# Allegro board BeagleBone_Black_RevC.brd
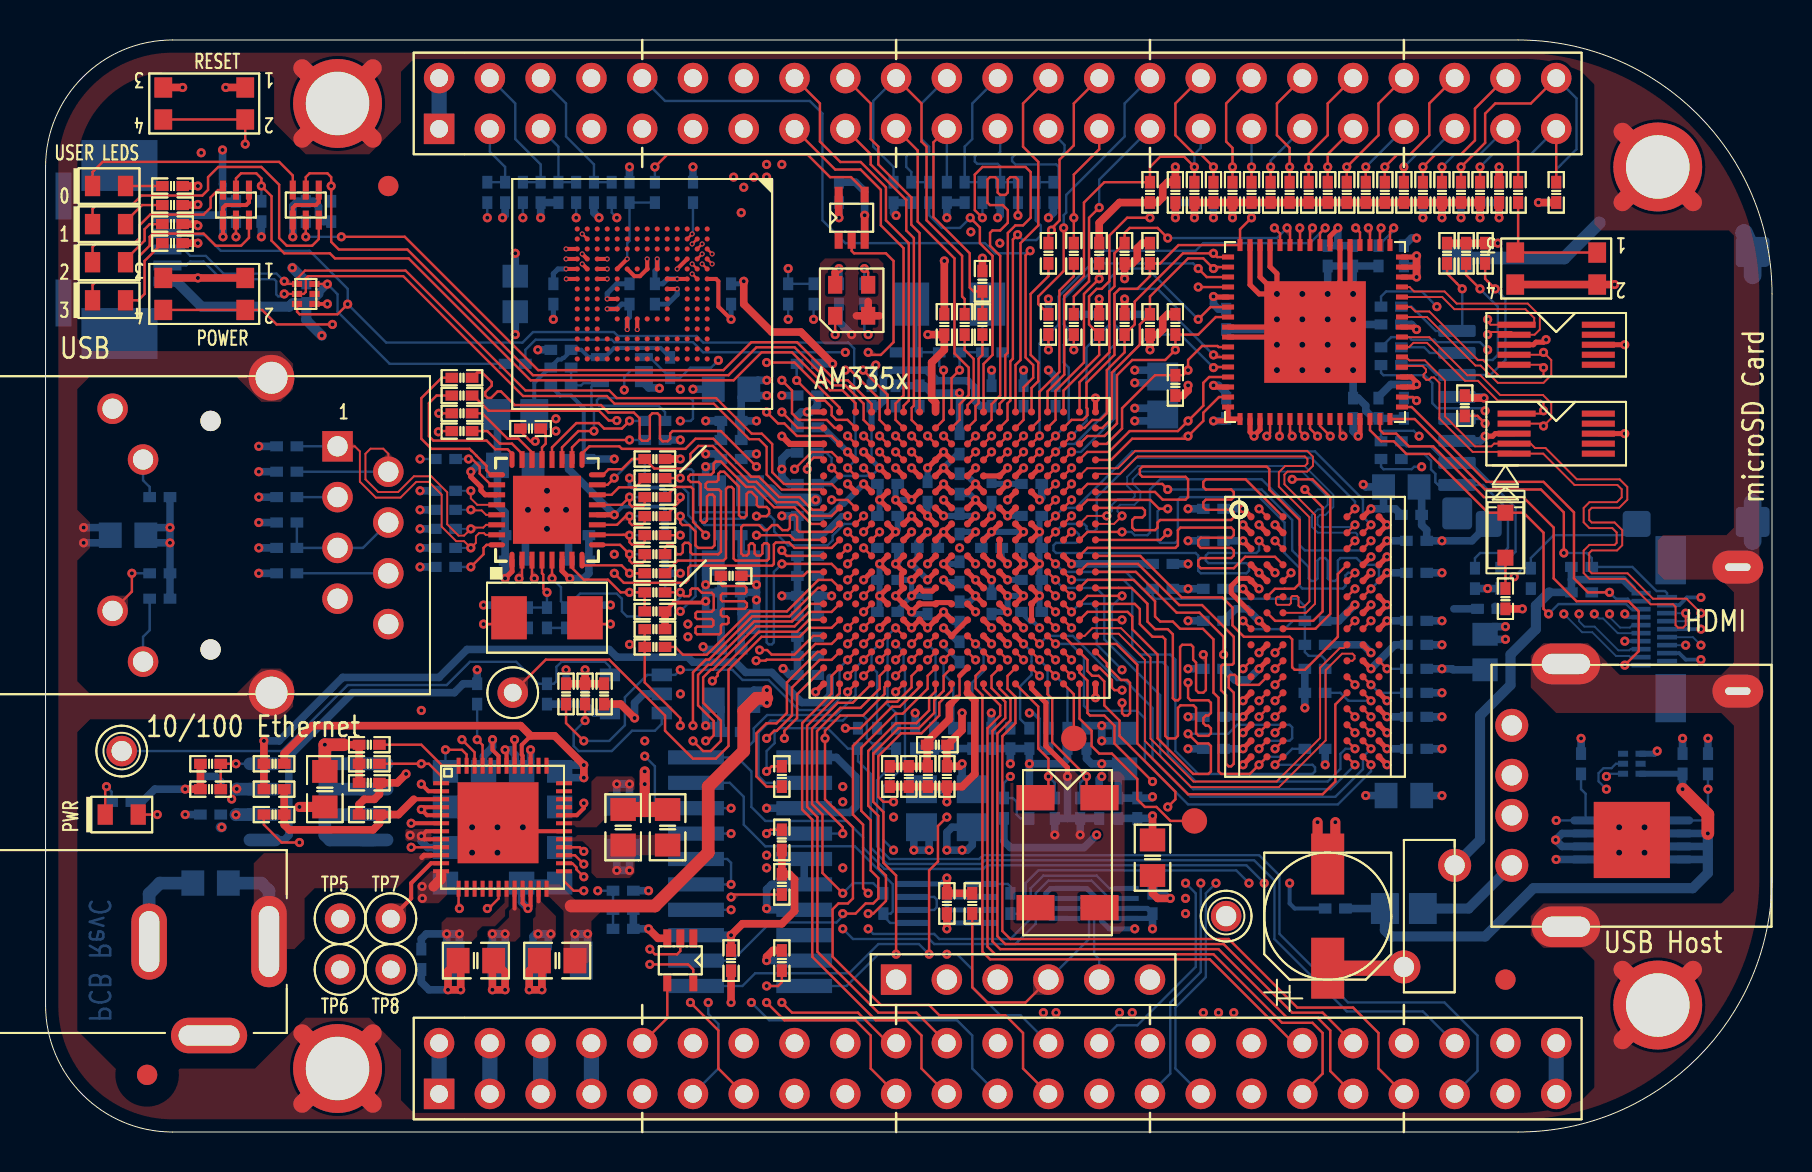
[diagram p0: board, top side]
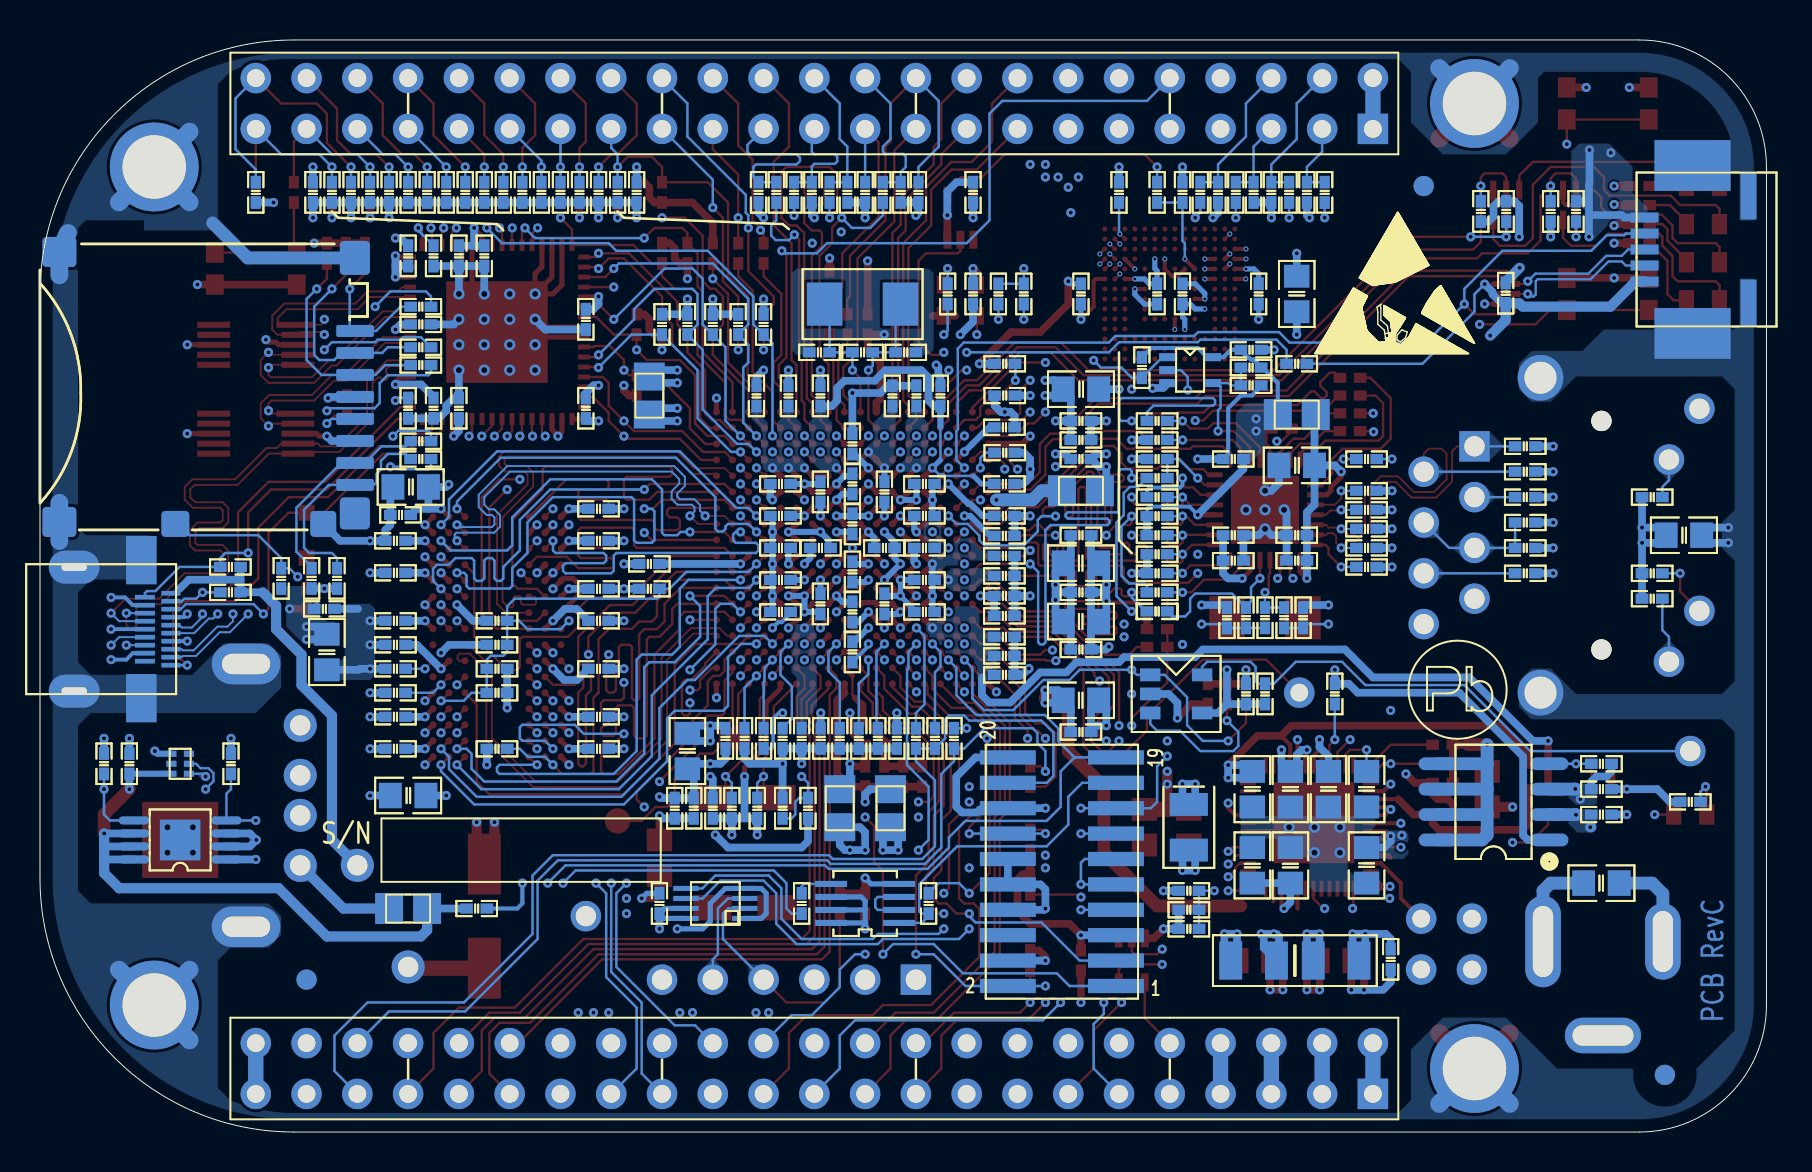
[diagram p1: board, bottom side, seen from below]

Outline 86.36 x 54.61 mm; copper layers: TOP, LYR2_GND, LYR3, LYR4, LYR5_PWR, BOTTOM. Coordinates in mm from the lower left corner of the outline.
Outline path: 0,48.26 0,6.35 arc(1.86,1.86) 6.35,0 73.66,0 arc(82.64,3.72) 86.36,12.7 86.36,41.91 arc(82.64,50.89) 73.66,54.61 6.35,54.61 arc(1.86,52.75) 0,48.26

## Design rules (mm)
constraint set DEFAULT: min track width 0.121
net group HDMI_TX0: nets HDMI_TX0+ HDMI_TX0-
net group HDMI_TX1: nets HDMI_TX1+ HDMI_TX1-
net group HDMI_TX2: nets HDMI_TX2+ HDMI_TX2-
net group HDMI_TXC: nets HDMI_TXC+ HDMI_TXC-
net group MMC1_CLK: nets AM3_MMC1_CLK MMC1_CLK
net group MMC1_DAT0: nets AM3_MMC1_DAT0 MMC1_DAT0
net group MMC1_DAT1: nets AM3_MMC1_DAT1 MMC1_DAT1
net group MMC1_DAT2: nets AM3_MMC1_DAT2 MMC1_DAT2
net group MMC1_DAT3: nets AM3_MMC1_DAT3 MMC1_DAT3
net group MMC1_DAT4: nets AM3_MMC1_DAT4 MMC1_DAT4
net group MMC1_DAT5: nets AM3_MMC1_DAT5 MMC1_DAT5
net group MMC1_DAT6: nets AM3_MMC1_DAT6 MMC1_DAT6
net group MMC1_DAT7: nets AM3_MMC1_DAT7 MMC1_DAT7
net group RX: nets RXN RXP
net group TX: nets TXN TXP
net group USB0: nets USB0_DM USB0_DP
net group USB1: nets USB1_DM USB1_DP
net group CLK: nets SD_CLK
net group DDR_ADD: nets DDR_A0 DDR_A1 DDR_A2 DDR_A3 DDR_A4 DDR_A5 DDR_A6 DDR_A7 DDR_A8 DDR_A9 DDR_A10 DDR_A11 DDR_A12 DDR_A13 DDR_A14 DDR_BA0 DDR_BA1 DDR_BA2 DDR_CASN DDR_CKE DDR_CLK DDR_CLKN DDR_CSN DDR_ODT DDR_RASN DDR_WEN
net group DDR_DQ0: nets DDR_D0 DDR_D1 DDR_D2 DDR_D3 DDR_D4 DDR_D5 DDR_D6 DDR_D7 DDR_DQM0 DDR_DQS0 DDR_DQSN0
net group DDR_DQ1: nets DDR_D8 DDR_D9 DDR_D10 DDR_D11 DDR_D12 DDR_D13 DDR_D14 DDR_D15 DDR_DQM1 DDR_DQS1 DDR_DQSN1
nets with their own width: min track width 0.203; nets USB1_VBUS

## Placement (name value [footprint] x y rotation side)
C1  10uF,16V  [805]  13.97 17.14 270 top
C2  10uF,16V  [805]  8.26 12.45 0 bottom
C3  100nF,16V  [402]  16.19 19.37 0 top
C4  10uF,16V  [805]  20 17.14 90 bottom
C5  10pF,50V  [0402]  30.48 25.15 0 top
C7  10uF,16V  [805]  23.81 13.34 270 bottom
C8  10uF,16V  [805]  25.72 13.34 270 bottom
C9  10uF,16V  [805]  21.53 8.57 180 top
C10  10uF,16V  [805]  20 13.34 90 bottom
C11  10uF,16V  [805]  28.89 15.24 270 top
C12  10uF,16V  [805]  25.59 8.57 0 top
C13  10uF,16V  [805]  23.81 17.14 90 bottom
C14  10uF,16V  [805]  25.72 17.14 90 bottom
C15  10uF,16V  [805]  21.91 17.14 90 bottom
C16  2.2uF,10V  [402]  16.19 17.46 180 top
C17  2.2uF,10V  [402]  8.26 15.88 180 bottom
C18  2.2uF,10V  [402]  16.19 18.41 180 top
C19  470pF,50V  [402]  8.26 18.41 180 top
C20  100nF,16V  [402]  8.26 17.14 180 bottom
C21  18pF,50V  [402]  50.48 16.19 90 bottom
C22  18pF,50V  [402]  51.75 16.19 90 bottom
C23  100nF,16V  [0402]  25.78 39.12 180 bottom
C24  2.2uF,10V  [402]  28.89 11.11 0 bottom
C25  18pF,50V  [402]  47.37 38.99 0 bottom
C26  18pF,50V  [402]  43.05 38.99 180 bottom
C27  100nF,16V  [402]  45.09 11.43 90 top
C28  100nF,16V  [402]  55.88 27.17 0 bottom
C29  100nF,16V  [402]  34.29 8.57 270 top
C30  100nF,16V  [402]  28.89 10.16 0 bottom
C31  100nF,16V  [402]  43.18 17.78 270 top
C32  1nF,50V  [402]  42.23 17.78 270 top
C33  100nF,16V  [402]  44.13 17.78 270 top
C34  100uF,10V  [RD205SMD_250D]  64.14 10.79 90 top
C35  100nF,16V  [402]  81.89 18.41 90 bottom
C36  100nF,16V  [402]  13.04 41.95 90 bottom
C37  100nF,16V  [402]  27.94 21.91 270 top
C38  100nF,16V  [402]  34.29 34.61 180 bottom
C39  10uF,16V  [805]  34.29 25.53 0 bottom
C40  10uF,16V  [805]  34.29 28.45 0 bottom
C41  100nF,16V  [402]  42.12 32.41 180 bottom
C42  100nF,16V  [402]  45.72 32.41 270 bottom
C43  100nF,16V  [402]  47.32 32.01 90 bottom
C44  100nF,16V  [402]  38.12 25.81 180 bottom
C45  100nF,16V  [402]  38.12 29.81 180 bottom
C46  100nF,16V  [402]  44.12 29.21 0 bottom
C47  100nF,16V  [402]  45.72 30.41 270 bottom
C48  100nF,16V  [402]  47.32 29.21 0 bottom
C49  100nF,16V  [402]  45.72 28.01 90 bottom
C50  100nF,16V  [402]  47.32 26.41 90 bottom
C51  100nF,16V  [402]  34.29 29.84 180 bottom
C52  100nF,16V  [402]  34.29 26.99 180 bottom
C53  100nF,16V  [402]  34.29 24.13 180 bottom
C54  100nF,16V  [402]  38.12 26.81 180 bottom
C55  10uF,16V  [805]  31.11 15.24 270 top
C56  100nF,16V  [402]  45.72 34.41 270 bottom
C57  100nF,16V  [402]  56.52 46.99 270 top
C58  100nF,16V  [402]  42.52 36.81 90 bottom
C59  100nF,16V  [402]  43.5 19.68 270 bottom
C60  100nF,16V  [402]  42.12 27.61 180 bottom
C61  100nF,16V  [402]  72.71 46.99 270 top
C62  10uF,16V  [805]  34.29 21.59 0 bottom
C63  100nF,16V  [402]  44.12 26.41 90 bottom
C64  100nF,16V  [402]  34.29 20 180 bottom
C65  100nF,16V  [402]  42.12 29.21 180 bottom
C66  100nF,16V  [402]  42.12 30.81 180 bottom
C67  100nF,16V  [402]  34.29 35.56 180 bottom
C68  100nF,16V  [402]  48.92 36.81 270 bottom
C69  100nF,16V  [402]  38.12 28.81 0 bottom
C70  100nF,16V  [402]  42.12 26.01 180 bottom
C71  100nF,16V  [402]  38.1 36.83 180 bottom
C72  100nF,16V  [402]  45.72 26.01 270 bottom
C73  100nF,16V  [402]  49.32 32.41 0 bottom
C74  100nF,16V  [402]  50.52 36.81 270 bottom
C75  100nF,16V  [402]  56.52 46.99 270 bottom
C76  100nF,16V  [402]  72.71 46.99 270 bottom
C77  10uF,16V  [805]  34.29 37.15 180 bottom
C78  100nF,16V  [402]  34.29 33.66 0 bottom
C79  100nF,16V  [402]  38.12 27.81 180 bottom
C80  100nF,16V  [402]  41.32 36.81 90 bottom
C81  100nF,16V  [402]  47.32 36.81 90 bottom
C82  100nF,16V  [402]  38.12 24.77 180 bottom
C83  100nF,16V  [402]  38.12 23.81 180 bottom
C84  100nF,16V  [402]  38.12 32.41 180 bottom
C85  100nF,16V  [402]  38.12 22.86 180 bottom
C86  100nF,16V  [402]  38.12 35.24 180 bottom
C87  100nF,16V  [402]  38.12 30.81 180 bottom
C88  100nF,16V  [402]  45.72 24.01 270 bottom
C89  1uF,10V  [402]  46.35 19.68 270 bottom
C90  1uF,10V  [402]  44.45 19.68 270 bottom
C91  1uF,10V  [402]  45.4 19.68 270 bottom
C92  100nF,16V  [402]  48.26 19.68 270 bottom
C93  100nF,16V  [402]  45.09 17.78 270 top
C94  100nF,16V  [402]  44.12 32.01 270 bottom
C95  10uF,16V  [805]  53.98 19.05 90 bottom
C96  10uF,16V  [805]  55.37 13.72 90 top
C97  100nF,16V  [402]  49.32 30.81 180 bottom
C98  100nF,16V  [402]  49.32 29.21 180 bottom
C99  100nF,16V  [402]  49.32 27.61 180 bottom
C100  100nF,16V  [402]  49.32 26.01 180 bottom
C101  100nF,16V  [402]  52.07 19.68 270 bottom
C102  100nF,16V  [402]  53.66 16.19 90 bottom
C103  100nF,16V  [402]  54.61 16.19 90 bottom
C104  1uF,10V  [402]  49.21 19.68 270 bottom
C105  100nF,16V  [402]  47.31 19.68 270 bottom
C106  1uF,10V  [402]  43.72 36.81 90 bottom
C107  100nF,16V  [402]  58.42 31.17 180 bottom
C108  100nF,16V  [402]  58.42 29.57 180 bottom
C109  100nF,16V  [402]  58.42 27.17 180 bottom
C110  100nF,16V  [402]  58.42 25.57 180 bottom
C111  100nF,16V  [402]  58.42 23.16 180 bottom
C112  100nF,16V  [402]  58.42 20.76 180 bottom
C113  100nF,16V  [402]  58.42 19.16 180 bottom
C114  100nF,16V  [402]  68.33 30.86 0 bottom
C115  100nF,16V  [402]  68.58 29.57 0 bottom
C116  100nF,16V  [402]  68.58 27.97 0 bottom
C117  100nF,16V  [402]  68.58 25.57 0 bottom
C118  10uF,16V  [805]  67.82 32.26 180 bottom
C119  100nF,16V  [402]  68.58 24.36 0 bottom
C120  100nF,16V  [402]  68.58 20.76 0 bottom
C121  100nF,16V  [402]  68.58 19.16 0 bottom
C122  10uF,16V  [805]  67.94 16.83 180 bottom
C123  1nF,50V  [402]  63.5 24.36 0 bottom
C124  100nF,16V  [402]  63.5 21.96 180 bottom
C125  2.2uF,10V  [402]  32.38 46.99 90 bottom
C126  10uF,16V  [805]  23.5 41.91 90 bottom
C127  100nF,16V  [402]  25.4 41.91 270 bottom
C128  100nF,16V  [402]  29.21 41.91 90 bottom
C129  100nF,16V  [402]  30.48 41.91 270 bottom
C130  100nF,16V  [402]  34.29 41.91 270 bottom
C131  100nF,16V  [402]  23.5 28.57 0 bottom
C132  100nF,16V  [402]  23.5 29.84 0 bottom
C133  10uF,16V  [805]  23.5 33.34 180 bottom
C134  1uF,10V  [402]  26.67 28.57 180 bottom
C135  100nF,16V  [402]  26.67 33.66 0 bottom
C136  470pF,50V  [0402]  26.67 29.84 180 bottom
C137  10pF,50V  [402]  12.06 34.29 180 bottom
C138  10pF,50V  [402]  12.06 33.02 180 bottom
C139  10pF,50V  [402]  12.06 31.75 180 bottom
C140  10pF,50V  [402]  12.06 27.94 180 bottom
C141  22nF,50V  [402]  12.06 30.48 180 bottom
C142  33pF,50V  [402]  23.18 25.72 90 bottom
C143  33pF,50V  [402]  26.99 25.72 90 bottom
C144  2.2uF,10V  [402]  59.05 40.64 270 bottom
C145  100nF,16V  [402]  59.05 36.2 270 bottom
C146  2.2uF,10V  [402]  64.14 43.81 270 bottom
C147  100nF,16V  [402]  65.41 36.2 90 bottom
C148  2.2uF,10V  [402]  65.41 43.81 270 bottom
C149  100nF,16V  [402]  67.94 43.81 90 bottom
C150  100nF,16V  [402]  67.31 40.39 180 bottom
C151  2.2uF,10V  [402]  66.67 36.2 270 bottom
C152  100nF,16V  [402]  26.04 21.91 90 bottom
C153  10uF,16V  [805]  72.01 24 270 bottom
C154  100nF,16V  [402]  72.14 26.16 180 bottom
C155  100nF,16V  [402]  55.37 11.43 270 bottom
C156  47pF,50V  [402]  55.24 43.94 90 top
C157  47pF,50V  [402]  53.98 40.39 90 top
C158  100nF,16V  [402]  39.69 46.99 90 bottom
C159  100nF,16V  [402]  39.69 41.91 270 bottom
C160  47pF,50V  [402]  55.24 40.39 270 top
C161  47pF,50V  [402]  51.44 40.39 90 bottom
C162  47pF,50V  [402]  52.7 40.39 90 bottom
C163  47pF,50V  [402]  56.52 40.39 90 top
C164  47pF,50V  [402]  50.16 40.39 90 bottom
C165  47pF,50V  [402]  55.24 46.99 270 top
C166  47pF,50V  [402]  52.7 40.39 90 top
C167  47pF,50V  [402]  53.98 43.94 270 top
C168  47pF,50V  [402]  52.7 43.94 90 top
C169  47pF,50V  [402]  56.52 37.34 270 top
C170  47pF,50V  [402]  53.98 40.39 90 bottom
C171  47pF,50V  [402]  75.56 46.99 270 bottom
C172  47pF,50V  [402]  55.24 40.39 90 bottom
C173  47pF,50V  [402]  75.56 46.99 270 top
C174  4.7uF,10V  [0402]  25.78 37.34 180 bottom
C175  10pF,50V  [0402]  46.86 42.55 90 top
D1  19-217/BHC-ZL1M2RY/3T  [LED_0603]  3.81 15.88 0 top
D2  19-217/BHC-ZL1M2RY/3T  [LED_0603]  3.17 47.31 0 top
D3  19-217/BHC-ZL1M2RY/3T  [LED_0603]  3.17 45.4 0 top
D4  19-217/BHC-ZL1M2RY/3T  [LED_0603]  3.17 43.5 0 top
D5  19-217/BHC-ZL1M2RY/3T  [LED_0603]  3.17 41.59 0 top
D6  TPD4S009DGSR  [TSSOP10]  75.56 34.92 270 top
D7  TPD4S009DGSR  [TSSOP10]  75.56 39.37 270 top
D8  RB751V40,115  [SOD323]  73.03 29.84 90 top
FB1  150R,800mA  [SM-7351-IND-0805]  34.29 32.07 0 bottom
FB2  150R,800mA  [SM-7351-IND-0805]  46.35 16.19 270 bottom
FB3  150R,800mA  [SM-7351-IND-0805]  43.81 16.19 270 bottom
FB4  150R,800mA  [SM-7351-IND-0805]  23.5 35.88 180 bottom
FB5  150R,800mA  [SM-7351-IND-0805]  55.88 36.83 270 bottom
FB7  150R,800mA  [SM-7351-IND-0805]  67.94 11.18 0 bottom
J1  Header 1x6Pin 2.54MM  [SIP6]  42.55 7.62 90 top
L1  2.2uH,1.3A  [2520]  21.53 8.57 180 bottom
L2  2.2uH,1.3A  [2520]  25.65 8.57 0 bottom
L3  2.2uH,1.3A  [2520]  28.89 15.24 270 bottom
MTG1  MHOLE  [MTGH200C125D_PL]  14.61 3.17 90 top
MTG2  MHOLE  [MTGH200C125D_PL]  80.64 6.35 90 top
MTG3  MHOLE  [MTGH200C125D_PL]  14.61 51.44 90 top
MTG4  MHOLE  [MTGH200C125D_PL]  80.64 48.26 90 top
NOREF  -  [unnamed]  5.08 2.86 270 top
NOREF#2  -  [#2]  -368.3 -256.54 0 top
NOREF#3  -  [unnamed]  73.03 7.62 270 top
NOREF#4  -  [#2]  80.64 6.35 0 top
NOREF#5  -  [#2]  81.92 52.07 0 top
NOREF#6  -  [#2]  -11.96 0 90 top
NOREF#7  -  [#2]  0 -11.96 0 top
NOREF#8  -  [#2]  0 0 0 top
NOREF#9  -  [#2]  -34.92 -47.62 0 top
NOREF#10  -  [#2]  14.61 3.17 0 top
NOREF#11  -  [#2]  80.64 48.26 0 top
NOREF#12  -  [#2]  86.36 27.94 0 top
NOREF#13  -  [#2]  6.35 54.61 0 top
NOREF#14  -  [unnamed]  17.14 47.31 270 top
NOREF#15  -  [#2]  14.61 51.44 0 top
NOREF#16  -  [#2]  319.53 -174.24 0 top
NOREF#17  -  [#2]  85.72 28.57 0 top
NOREF#18  -  [#2]  80.64 6.35 0 top
NOREF#19  -  [#2]  86.36 39.69 0 top
NOREF#20  -  [#2]  -368.17 -256.47 0 top
NOREF#21  -  [#2]  14.61 3.17 0 top
NOREF#22  -  [#2]  86.36 12.7 0 top
NOREF#23  -  [#2]  85.72 28.57 0 top
NOREF#24  -  [#2]  85.72 39.05 0 top
NOREF#25  -  [#2]  0 0 0 top
NOREF#26  -  [unnamed]  73.03 7.62 270 bottom
NOREF#27  -  [unnamed]  17.14 47.31 270 bottom
NOREF#28  -  [#2]  1.91 53.34 180 bottom
NOREF#29  -  [unnamed]  5.08 2.86 270 bottom
P1  DC630-20D01  [CONN3-PWR-PJ102A]  11.18 9.53 180 top
P2  Heaader 2x10 1.27mm  [HEADER10X2_SMD]  35.24 13.02 90 bottom
P3  UB11123-4H9-4F  [USB_A_SH]  73.34 13.34 90 top
P4  UX60SC-MB-5ST(80)  [USB5MINI_4SHIELDED_SMD-5]  6.1 44.13 0 bottom
P5  LPJ0011BBNL  [RJ45-7499010211A]  14.61 34.29 270 top
P6  10118241-001RLF  [CONN19_HDMI]  84.65 25.15 270 bottom
P8  Female Header 2x23Pin 2.54MM  [HEADER23X2]  19.68 50.16 0 top
P9  Female Header 2x23Pin 2.54MM  [HEADER23X2]  19.68 1.91 0 top
P10  YL004-030-001  [MICRO_SD_15X14_3X1_8MM]  70.61 31.26 90 bottom
Q1  DDC114YU-7-F  [SMINI6-F3-B]  13.02 46.35 180 top
Q2  DDC114YU-7-F  [SMINI6-F3-B]  9.53 46.35 180 top
R1  100K,1%  [402]  21.59 21.91 270 bottom
R2  33R,5%  [0402]  67.31 41.27 0 bottom
R3  1.5K,1%  [402]  26.04 21.91 270 top
R4  1.5K,1%  [402]  26.99 21.91 270 top
R5  0R,5%  [402]  16.19 15.88 180 top
R6  0R,5%  [402]  18.8 8.64 270 bottom
R7  0R,5%  [402]  11.43 15.88 180 top
R8  0R,5%  [402]  11.43 17.14 180 top
R9  0R,5%  [402]  11.43 18.41 0 top
R10  470K,1%  [402]  8.26 17.14 180 top
R11  280K,1%  [402]  8.26 18.41 0 bottom
R12  470R,5%  [402]  3.81 16.51 180 bottom
R13  33R,5%  [0402]  67.31 39.24 0 bottom
R14  10K,1%  [402]  28.89 12.06 180 bottom
R15  33R,5%  [0402]  67.31 38.35 0 bottom
R16  33R,5%  [0402]  30.48 24.26 180 top
R17  1M,1%  [402]  45.21 38.99 180 bottom
R18  33R,5%  [0402]  41.91 11.43 270 bottom
R19  0R,5%  [402]  41.59 19.68 270 bottom
R20  0R,5%  [402]  42.55 19.68 90 bottom
R21  33R,5%  [0402]  48.26 11.43 270 bottom
R22  49.9R,1%  [402]  55.88 28.41 180 bottom
R23  4.7K,1%  [402]  36.83 12.38 270 top
R24  4.7K,1%  [402]  36.83 14.61 90 top
R25  4.7K,1%  [402]  36.83 8.57 90 top
R26  4.7K,1%  [402]  50.16 19.68 90 bottom
R27  0R,5%  [402]  44.61 19.37 180 top
R28  33R,5%  [0402]  34.29 27.81 180 top
R29  0R,5%  [402]  44.96 40.39 90 top
R30  0R,5%  [402]  52.7 16.19 270 bottom
R31  33R,5%  [0402]  67.31 34.54 0 bottom
R32  33R,5%  [0402]  67.31 33.66 0 bottom
R33  10K,1%  [0402]  25.78 38.23 0 bottom
R34  10K,1%  [0402]  31.24 38.23 270 bottom
R35  33R,5%  [0402]  46.86 40.39 90 top
R36  33R,5%  [0402]  45.97 40.39 90 top
R37  0R,5%  [0402]  64.52 11.18 0 bottom
R38  33R,5%  [0402]  24.26 35.18 0 top
R39  33R,5%  [0402]  20.83 35.94 0 top
R40  33R,5%  [0402]  20.83 35.05 0 top
R41  33R,5%  [0402]  20.83 36.83 180 top
R42  33R,5%  [0402]  20.83 37.72 180 top
R43  33R,5%  [0402]  49.53 46.99 90 bottom
R44  33R,5%  [0402]  46.86 46.99 90 bottom
R45  22R,1%  [0402]  50.16 43.94 90 top
R46  0R,5%  [0402]  51.44 43.94 90 top
R47  0R,5%  [0402]  51.44 40.39 90 top
R48  0R,5%  [0402]  50.16 40.39 90 top
R49  0R,5%  [402]  38.1 33.97 0 bottom
R50  0R,5%  [402]  36.83 17.78 270 top
R51  0R,5%  [402]  40.64 19.68 90 bottom
R52  10K,1%  [402]  83.16 18.41 270 bottom
R53  10K,1%  [402]  76.81 18.41 90 bottom
R54  10K,1%  [402]  51.12 19.68 90 bottom
R55  100K,1%  [402]  58.42 46.99 90 bottom
R56  100K,1%  [402]  57.47 46.99 90 bottom
R57  100K,1%  [402]  60.33 46.99 90 bottom
R58  100K,1%  [402]  61.28 46.99 90 bottom
R59  100K,1%  [402]  59.37 46.99 90 bottom
R60  100K,1%  [402]  62.23 46.99 90 bottom
R61  100K,1%  [402]  63.18 46.99 90 bottom
R62  100K,1%  [402]  64.14 46.99 90 bottom
R63  100K,1%  [402]  65.09 46.99 90 bottom
R64  100K,1%  [402]  66.04 46.99 90 bottom
R65  100K,1%  [402]  66.99 46.99 90 bottom
R66  100K,1%  [402]  67.94 46.99 90 bottom
R67  100K,1%  [402]  68.9 46.99 90 bottom
R68  100K,1%  [402]  69.85 46.99 90 bottom
R69  100K,1%  [402]  70.8 46.99 90 bottom
R70  100K,1%  [402]  71.75 46.99 90 bottom
R71  2.2K,5%  [402]  6.35 44.45 180 top
R72  2.2K,5%  [402]  6.35 47.31 180 top
R73  2.2K,5%  [402]  6.35 46.35 180 top
R74  2.2K,5%  [402]  6.35 45.4 180 top
R75  100R,1%  [402]  73.66 46.99 270 top
R76  100K,1%  [402]  13.02 46.04 90 bottom
R77  100K,1%  [402]  14.29 46.04 270 bottom
R78  100K,1%  [402]  9.53 46.04 90 bottom
R79  100K,1%  [402]  10.79 46.04 270 bottom
R80  100K,1%  [402]  58.42 46.99 270 top
R81  100K,1%  [402]  57.47 46.99 270 top
R82  100K,1%  [402]  60.33 46.99 270 top
R83  100K,1%  [402]  61.28 46.99 270 top
R84  100K,1%  [402]  59.37 46.99 270 top
R85  100K,1%  [402]  62.23 46.99 270 top
R86  100K,1%  [402]  63.18 46.99 270 top
R87  100K,1%  [402]  64.14 46.99 270 top
R88  100K,1%  [402]  65.09 46.99 270 top
R89  100K,1%  [402]  66.04 46.99 270 top
R90  100K,1%  [402]  66.99 46.99 270 top
R91  100K,1%  [402]  67.94 46.99 270 top
R92  100K,1%  [402]  68.9 46.99 270 top
R93  100K,1%  [402]  69.85 46.99 270 top
R94  100K,1%  [402]  70.8 46.99 270 top
R95  100K,1%  [402]  71.75 46.99 270 top
R96  10K,1%  [402]  68.58 23.16 180 bottom
R97  1.5K,1%  [402]  63.5 19.16 180 bottom
R98  10K,1%  [402]  63.5 25.57 180 bottom
R99  240R,1%  [0402]  68.58 21.96 180 bottom
R100  10K,1%  [402]  63.5 23.16 180 bottom
R101  10K,1%  [402]  50.42 46.99 90 bottom
R102  10K,1%  [402]  45.97 46.99 90 bottom
R103  10K,1%  [402]  25.65 46.99 90 bottom
R104  10K,1%  [402]  27.43 46.99 90 bottom
R105  10K,1%  [402]  47.75 46.99 90 bottom
R106  10K,1%  [402]  43.31 46.99 90 bottom
R107  10K,1%  [402]  22.99 46.99 90 bottom
R108  10K,1%  [402]  24.77 46.99 90 bottom
R109  10K,1%  [402]  42.42 46.99 90 bottom
R110  10K,1%  [402]  45.09 46.99 90 bottom
R111  10K,1%  [402]  29.21 46.99 270 bottom
R112  1.5K,1%  [402]  30.48 30.8 0 bottom
R113  1.5K,1%  [402]  30.48 33.66 0 bottom
R114  1.5K,1%  [402]  30.48 29.84 0 bottom
R115  10K,1%  [402]  30.48 31.75 0 bottom
R116  10K,1%  [402]  30.48 27.94 0 bottom
R117  10K,1%  [402]  30.48 28.89 0 bottom
R118  10K,1%  [402]  30.48 26.04 0 top
R119  1.5K,1%  [402]  30.48 33.66 180 top
R120  49.9R,1%  [402]  20 29.21 180 bottom
R121  49.9R,1%  [402]  20 30.16 180 bottom
R122  49.9R,1%  [402]  20 31.11 180 bottom
R123  49.9R,1%  [402]  20 32.07 180 bottom
R124  10R,1%  [402]  30.48 26.99 180 top
R125  100R,1%  [402]  30.48 27.94 180 top
R126  100R,1%  [402]  30.48 28.89 180 top
R127  100R,1%  [402]  30.48 29.84 180 top
R128  100R,1%  [402]  30.48 30.8 180 top
R129  100R,1%  [402]  20 33.66 0 bottom
R130  470R,5%  [402]  5.71 27.94 180 bottom
R131  100R,1%  [402]  30.48 26.99 180 bottom
R132  470R,5%  [402]  5.71 31.75 180 bottom
R133  100R,1%  [402]  30.48 31.75 180 top
R134  100R,1%  [402]  30.48 35.56 180 bottom
R135  10K,1%  [402]  5.71 26.67 0 bottom
R136  0.1R,5%  [805]  4.13 29.84 180 bottom
R137  0R,5%  [402]  12.06 29.21 180 bottom
R138  100R,1%  [402]  30.48 32.7 180 bottom
R139  100R,1%  [402]  30.48 32.7 180 top
R140  0R,5%  [402]  30.48 26.04 180 bottom
R141  1M,1%  [402]  25.08 25.72 270 bottom
R142  0R,5%  [402]  26.04 25.72 90 bottom
R143  10R,1%  [402]  24.13 25.72 270 bottom
R144  12.1K,1%  [402]  20 28.26 180 bottom
R145  10K,1%  [402]  30.48 34.61 0 bottom
R146  1.5K,1%  [402]  76.83 26.99 0 bottom
R147  1.5K,1%  [402]  76.83 28.26 0 bottom
R148  10K,1%  [402]  67.94 36.2 270 bottom
R149  0R,5%  [402]  66.67 43.81 270 bottom
R150  10K,1%  [402]  70.1 43.94 270 top
R151  10K,1%  [402]  72.01 43.94 270 top
R152  10K,1%  [402]  70.99 36.32 270 top
R153  10K,1%  [402]  72.77 27.69 90 bottom
R154  10K,1%  [402]  71.5 27.69 90 bottom
R155  10K,1%  [402]  71.06 43.94 270 top
R156  10K,1%  [402]  25.08 21.91 90 bottom
R157  10K,1%  [402]  74.3 27.69 270 bottom
R158  10K,1%  [402]  38.1 38.42 180 bottom
R159  0R,5%  [402]  23.5 38.42 0 bottom
R160  0R,5%  [402]  38.42 41.91 90 bottom
R161  0R,5%  [402]  37.15 41.91 90 bottom
R162  0R,5%  [402]  30.48 46.99 270 bottom
R163  4.7K,1%  [402]  47.94 16.19 90 bottom
R164  4.7K,1%  [402]  49.21 16.19 90 bottom
R165  100K,1%  [402]  46.35 11.43 90 top
R166  27K,1%  [402]  73.03 26.67 270 top
R167  33R,5%  [0402]  40.96 41.91 270 bottom
R168  33R,5%  [0402]  26.54 46.99 90 bottom
R169  33R,5%  [0402]  28.32 46.99 90 bottom
R170  33R,5%  [0402]  48.64 46.99 90 bottom
R171  33R,5%  [0402]  44.2 46.99 90 bottom
R172  33R,5%  [0402]  22.1 46.99 90 bottom
R173  33R,5%  [0402]  23.88 46.99 90 bottom
RT1  RXEF010  [POLYSW200-5638-310]  70.48 13.34 90 top
S1  KMR231GLFS  [SW4SMD_63X161LS]  7.94 51.44 180 top
S2  KMR231GLFS  [SW4SMD_63X161LS]  75.56 43.18 180 top
S3  KMR231GLFS  [SW4SMD_63X161LS]  7.94 41.91 180 top
TP1  Test Point  [TP1-8040]  59.05 10.79 0 top
TP2  Test Point  [TP60C_SMD]  57.47 15.56 0 top
TP3  Test Point  [TP60C_SMD]  51.44 19.68 0 top
TP4  Test Point  [TP1-8040]  3.81 19.05 0 top
TP5  Test Point  [TP60C33D]  14.73 10.67 0 top
TP6  Test Point  [TP60C33D]  14.73 8.13 0 top
TP7  Test Point  [TP60C33D]  17.27 10.67 0 top
TP8  Test Point  [TP60C33D]  17.27 8.13 0 top
TP9  Test Point  [TP60C33D]  23.37 21.97 0 top
U1  SN74AHC1G09DCKR  [DCK5_2P15X1P4]  28.83 38.1 270 bottom
U2  TPS65217CRSLR  [U_48_RSL]  22.86 15.24 0 top
U3  SN74LVC1G06DCKR  [DCK5_2P15X1P4]  40.32 45.72 0 top
U4  TL5209DR  [SO8-25X75]  13.65 16.51 90 bottom
U5  AM3358BZCZ100  [AM33XX_15X15]  45.72 29.21 180 top
U6  SN74LVC1G74DCTR  [SOP8_DCT]  45.09 11.43 90 bottom
U7  24LC32AT-I/OT  [SOT23-5]  29.53 21.91 270 bottom
U8  TPS2051BDGNR  [DGN-16X60]  79.35 14.61 90 bottom
U9  TPD4S012DRYR  [U_6_DRY]  79.35 18.41 90 bottom
U10  TPD4S012DRYR  [U_6_DRY]  13.02 41.91 270 top
U11  TDA19988BHN/C1,557  [QFN64S9X9P5]  63.5 40.01 0 top
U12  D2516ECMDXGJD-U  [BGA96_T9_P8_9X14]  63.5 24.77 0 top
U13  EMMC04G-M627  [BGA153_P14_P5_11P5X13]  29.84 41.91 270 top
U14  LAN8710A-EZC-TR  [QFN32_5X5MM_EP3P3MM]  25.08 31.11 0 top
U15  SN74LVC2G241DCUR  [U_8_DCU]  52.58 11.43 90 bottom
U16  SN74LVC1G07DCKR  [DCK5_2P15X1P4]  31.75 8.59 180 top
Y1  32.768KHz,12.5pF  [XTAL4_126-216SMD]  51.12 13.97 270 top
Y2  24MHz,20pF  [XTAL150SMD_125X196]  45.21 41.4 0 bottom
Y3  25MHz,20pF  [XTAL150SMD_125X196]  25.08 25.72 180 top
Y4  24.576MHz  [OSC4_61X65LS_79X98SMD]  40.32 41.59 0 top

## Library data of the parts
C1 C2 C4 C7-C15 C39 C40 C55 C62 C77 C95 C96 C118 C122 C126 C133 C153 = CAP_10uF_Y5V_10V_10%_0805
C3 C20 C23 C27-C31 C33 C35-C38 C41-C54 C56-C61 C63-C76 C78-C88 C92-C94 C97-C103 C105 C107-C117 C119-C121 C124 C127-C132 C135 C145 C147 C149 C150 C152 C154-C173 = CAP_0.1uF_X5R_6.3V_20% 0201
C5 C175 = CC
C16-C18 C125 C144 C146 C148 C151 = CAP_2.2uF_X5R_6.3V_10%_0402
C19 = CAP_470PF_X7R_25V_10%_0402
C21 C22 C25 C26 = CAP_18PF_COG_50V_5%_0402
C24 C89-C91 C104 C106 C134 = CAP_1.0UF_X5R_10V_10%_0402
C32 C123 = CAP_0.001_X7R_50V_5%_0402
C34 = CAP_100UF_TANT_6.3V_3528-21
C136 = 470pF/5%/50V/C0G/0603_0
C137-C140 = CAP_0402_100pF_COG_50V
C141 = CAP_0402_0.1uf_X5R_10V
C142 C143 C174 = CAP_30PF_COG_50V_5%_0402
D1-D5 = LED_LTST-C150GKT_0
D6 D7 = 32CTQ030/TO_1
D8 = DIO_SR305_TH_0
FB1-FB4 FB7 = FER_180_200_0
FB5 = FER_180_200_0805
J1 = HEADER 6: User Part Number: ***
L1-L3 = IND_2.2uH_2.6A_10%_SMD
MTG1-MTG4 = MHOLE
P1 = Power_Jack: Tolerance: X; User Part Number: X
P2 = HDR_10x2_CJTAG_0
P3 = CONN_54819-0578_2: User Part Number: PART#; Tolerance: TOL
P4 = MINI-USB-AB-SOCKET
P5 = CONN_RJ45_MAG_WE_0
P6 = CONN_HDMI_TYPED: User Part Number: PRT#; Tolerance: TOL*
P8 P9 = HDR_46_F_2_0.1_0.1
P10 = MicroSD Card_10+4P
Q1 Q2 = RN1907
R1 R37 R55-R70 R75-R95 R165 = RES_100K_1/16W_1%_0402
R2 R13 R15 R16 R28 R31 R32 R36 R45 R46 R48 R167 = RES_33_0402
R3 R4 R119 R146 R147 = RES_1.5K_1/16W_5%_0402
R5-R9 R23-R26 R50 R51 R112-R118 R159-R164 = RES_4.75K_1/16W_1%_0402
R10 R12 R71-R74 R130 R132 = RES_470_1/10W_5%_0402
R11 = RES_470_1/10W_5%_0402: signal model: 33OHMRESISTOR1_16W5_0402_SM_735_33
R14 = RES_10K_1/16W_1%_0402: signal model: 33OHMRESISTOR1_16W5_0402_SM_735_33
R17 = RES_1M_1/16W_1%_0402: signal model: 33OHMRESISTOR1_16W5_0402_SM_735_33
R18 R21 R47 = RES_33_0402: signal model: 33OHMRESISTOR1_16W5_0402_SM_735_33
R19 R27 R29 R30 R140 R142 R149 R156 = RES_0_1/16W_1%_0402
R20 = RES_0_1/16W_1%_0402: signal model: 33OHMRESISTOR1_16W5_0402_SM_735_33
R22 R38-R42 R120-R123 = RES_4.7K_0402
R33 R34 R52-R54 R96-R98 R100-R111 R135 R137 R143 R145 R148 R150-R155 R157 R158 = RES_10K_1/16W_1%_0402
R35 R43 R44 R168-R173 = RES_33_0402: signal model: RES_33_0402_0402_33R_5%_33R_5%
R49 = RES_100K_1/16W_1%_0402: signal model: 33OHMRESISTOR1_16W5_0402_SM_735_33
R99 = Res
R124-R126 R129 R134 R138 = 100-1/10W-1%-0603_4
R127 R128 R131 R133 R139 = RES_100_1/10W_5%_0402
R136 = RES_0.1_0805
R141 = RES_1M_1/16W_1%_0402
R144 = RES_12.1K_1/16W_1%_0402
R166 = RES_22.6K_1/16W_1%_0402
RT1 = PTC_RXEF010: User Part Number: X; Tolerance: X
S1 S3 = SW_KT11P2JM_2
S2 = SW_KT11P2JM_1
TP1-TP9 = TESTPT1
U1 = SN74AHC1G09DCKR
U2 = PWR_TPS65217_2
U3 = IC_SN74LVC1G06DCK_0
U4 = PWR_TLV70233DBV_0: Tolerance: X; User Part Number: X
U5 = IC_AM335X_ZCZ
U6 = IC_SN74AUC1G74
U7 = MEM_24LC32_SOT23-5
U8 = TPS2061_1: User Part Number: X; Tolerance: X
U9 U10 = PROT_TPD4S012
U11 = IC_TDA19988_HVQFN64_5
U12 = MT47H256M8_7
U13 = eMMC_153-ball_WFBGA
U14 = LAN8710 QFN32_1
U15 = IC_SN74LVC2G241_1
U16 = IC_SN74LVC1G07DCK
Y1 = CRYS_32_768KHz_SMD32_1
Y2 = CRYS_24MHz_SCC_0
Y3 = Suntsu ITEMP 25MHz _0.005% 20pf
Y4 = OSC_12MHz_1.3V: Tolerance: TOL*; User Part Number: P/N*

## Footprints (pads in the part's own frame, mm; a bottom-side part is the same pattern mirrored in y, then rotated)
402
  rect 0.635x0.508 smd: 1(-0.508,0) 2(0.508,0)
0402
  rect 0.635x0.508 smd: 1(-0.508,0) 2(0.508,0)
805
  rect 1.143x1.27 smd: 1(-0.889,0) 2(0.889,0)
2520
  rect 1.143x1.905 smd: 1(-1.143,0) 2(1.143,0)
AM33XX_15X15
  round 0.356 smd: A1(-6.8,6.8) A2(-6,6.8) A3(-5.2,6.8) A4(-4.4,6.8) A5(-3.6,6.8) A6(-2.8,6.8) A7(-2,6.8) A8(-1.2,6.8) A9(-0.4,6.8) A10(0.4,6.8) A11(1.2,6.8) A12(2,6.8) A13(2.8,6.8) A14(3.6,6.8) A15(4.4,6.8) A16(5.2,6.8) A17(6,6.8) A18(6.8,6.8) B1(-6.8,6) B2(-6,6) B3(-5.2,6) B4(-4.4,6) B5(-3.6,6) B6(-2.8,6) B7(-2,6) B8(-1.2,6) B9(-0.4,6) B10(0.4,6) B11(1.2,6) B12(2,6) B13(2.8,6) B14(3.6,6) B15(4.4,6) B16(5.2,6) B17(6,6) B18(6.8,6) C1(-6.8,5.2) C2(-6,5.2) C3(-5.2,5.2) C4(-4.4,5.2) C5(-3.6,5.2) C6(-2.8,5.2) C7(-2,5.2) C8(-1.2,5.2) C9(-0.4,5.2) C10(0.4,5.2) C11(1.2,5.2) C12(2,5.2) C13(2.8,5.2) C14(3.6,5.2) C15(4.4,5.2) C16(5.2,5.2) C17(6,5.2) C18(6.8,5.2) D1(-6.8,4.4) D2(-6,4.4) D3(-5.2,4.4) D4(-4.4,4.4) D5(-3.6,4.4) D6(-2.8,4.4) D7(-2,4.4) D8(-1.2,4.4) D9(-0.4,4.4) D10(0.4,4.4) D11(1.2,4.4) D12(2,4.4) D13(2.8,4.4) D14(3.6,4.4) D15(4.4,4.4) D16(5.2,4.4) D17(6,4.4) D18(6.8,4.4) E1(-6.8,3.6) E2(-6,3.6) E3(-5.2,3.6) E4(-4.4,3.6) E5(-3.6,3.6) E6(-2.8,3.6) E7(-2,3.6) E8(-1.2,3.6) E9(-0.4,3.6) E10(0.4,3.6) E11(1.2,3.6) E12(2,3.6) E13(2.8,3.6) E14(3.6,3.6) E15(4.4,3.6) E16(5.2,3.6) E17(6,3.6) E18(6.8,3.6) F1(-6.8,2.8) F2(-6,2.8) F3(-5.2,2.8) F4(-4.4,2.8) F5(-3.6,2.8) F6(-2.8,2.8) F7(-2,2.8) F8(-1.2,2.8) F9(-0.4,2.8) F10(0.4,2.8) F11(1.2,2.8) F12(2,2.8) F13(2.8,2.8) F14(3.6,2.8) F15(4.4,2.8) F16(5.2,2.8) F17(6,2.8) F18(6.8,2.8) G1(-6.8,2) G2(-6,2) G3(-5.2,2) G4(-4.4,2) G5(-3.6,2) G6(-2.8,2) G7(-2,2) G8(-1.2,2) G9(-0.4,2) G10(0.4,2) G11(1.2,2) G12(2,2) G13(2.8,2) G14(3.6,2) G15(4.4,2) G16(5.2,2) G17(6,2) G18(6.8,2) H1(-6.8,1.2) H2(-6,1.2) H3(-5.2,1.2) H4(-4.4,1.2) H5(-3.6,1.2) H6(-2.8,1.2) H7(-2,1.2) H8(-1.2,1.2) H9(-0.4,1.2) H10(0.4,1.2) H11(1.2,1.2) H12(2,1.2) H13(2.8,1.2) H14(3.6,1.2) H15(4.4,1.2) H16(5.2,1.2) H17(6,1.2) H18(6.8,1.2) J1(-6.8,0.4) J2(-6,0.4) J3(-5.2,0.4) J4(-4.4,0.4) J5(-3.6,0.4) J6(-2.8,0.4) J7(-2,0.4) J8(-1.2,0.4) J9(-0.4,0.4) J10(0.4,0.4) J11(1.2,0.4) J12(2,0.4) J13(2.8,0.4) J14(3.6,0.4) J15(4.4,0.4) J16(5.2,0.4) J17(6,0.4) J18(6.8,0.4) K1(-6.8,-0.4) K2(-6,-0.4) K3(-5.2,-0.4) K4(-4.4,-0.4) K5(-3.6,-0.4) K6(-2.8,-0.4) K7(-2,-0.4) K8(-1.2,-0.4) K9(-0.4,-0.4) K10(0.4,-0.4) K11(1.2,-0.4) K12(2,-0.4) K13(2.8,-0.4) K14(3.6,-0.4) K15(4.4,-0.4) K16(5.2,-0.4) K17(6,-0.4) K18(6.8,-0.4) L1(-6.8,-1.2) L2(-6,-1.2) L3(-5.2,-1.2) L4(-4.4,-1.2) L5(-3.6,-1.2) L6(-2.8,-1.2) L7(-2,-1.2) L8(-1.2,-1.2) L9(-0.4,-1.2) L10(0.4,-1.2) L11(1.2,-1.2) L12(2,-1.2) L13(2.8,-1.2) L14(3.6,-1.2) L15(4.4,-1.2) L16(5.2,-1.2) L17(6,-1.2) L18(6.8,-1.2) M1(-6.8,-2) M2(-6,-2) M3(-5.2,-2) M4(-4.4,-2) M5(-3.6,-2) M6(-2.8,-2) M7(-2,-2) M8(-1.2,-2) M9(-0.4,-2) M10(0.4,-2) M11(1.2,-2) M12(2,-2) M13(2.8,-2) M14(3.6,-2) M15(4.4,-2) M16(5.2,-2) M17(6,-2) M18(6.8,-2) N1(-6.8,-2.8) N2(-6,-2.8) N3(-5.2,-2.8) N4(-4.4,-2.8) N5(-3.6,-2.8) N6(-2.8,-2.8) N7(-2,-2.8) N8(-1.2,-2.8) N9(-0.4,-2.8) N10(0.4,-2.8) N11(1.2,-2.8) N12(2,-2.8) N13(2.8,-2.8) N14(3.6,-2.8) N15(4.4,-2.8) N16(5.2,-2.8) N17(6,-2.8) N18(6.8,-2.8) P1(-6.8,-3.6) P2(-6,-3.6) P3(-5.2,-3.6) P4(-4.4,-3.6) P5(-3.6,-3.6) P6(-2.8,-3.6) P7(-2,-3.6) P8(-1.2,-3.6) P9(-0.4,-3.6) P10(0.4,-3.6) P11(1.2,-3.6) P12(2,-3.6) P13(2.8,-3.6) P14(3.6,-3.6) P15(4.4,-3.6) P16(5.2,-3.6) P17(6,-3.6) P18(6.8,-3.6) R1(-6.8,-4.4) R2(-6,-4.4) R3(-5.2,-4.4) R4(-4.4,-4.4) R5(-3.6,-4.4) R6(-2.8,-4.4) R7(-2,-4.4) R8(-1.2,-4.4) R9(-0.4,-4.4) R10(0.4,-4.4) R11(1.2,-4.4) R12(2,-4.4) R13(2.8,-4.4) R14(3.6,-4.4) R15(4.4,-4.4) R16(5.2,-4.4) R17(6,-4.4) R18(6.8,-4.4) T1(-6.8,-5.2) T2(-6,-5.2) T3(-5.2,-5.2) T4(-4.4,-5.2) T5(-3.6,-5.2) T6(-2.8,-5.2) T7(-2,-5.2) T8(-1.2,-5.2) T9(-0.4,-5.2) T10(0.4,-5.2) T11(1.2,-5.2) T12(2,-5.2) T13(2.8,-5.2) T14(3.6,-5.2) T15(4.4,-5.2) T16(5.2,-5.2) T17(6,-5.2) T18(6.8,-5.2) U1(-6.8,-6) U2(-6,-6) U3(-5.2,-6) U4(-4.4,-6) U5(-3.6,-6) U6(-2.8,-6) U7(-2,-6) U8(-1.2,-6) U9(-0.4,-6) U10(0.4,-6) U11(1.2,-6) U12(2,-6) U13(2.8,-6) U14(3.6,-6) U15(4.4,-6) U16(5.2,-6) U17(6,-6) U18(6.8,-6) V1(-6.8,-6.8) V2(-6,-6.8) V3(-5.2,-6.8) V4(-4.4,-6.8) V5(-3.6,-6.8) V6(-2.8,-6.8) V7(-2,-6.8) V8(-1.2,-6.8) V9(-0.4,-6.8) V10(0.4,-6.8) V11(1.2,-6.8) V12(2,-6.8) V13(2.8,-6.8) V14(3.6,-6.8) V15(4.4,-6.8) V16(5.2,-6.8) V17(6,-6.8) V18(6.8,-6.8)
BGA96_T9_P8_9X14
  round 0.356 smd: A1(-3.2,6.001) A2(-2.4,6.001) A3(-1.6,6.001) A7(1.6,6.001) A8(2.4,6.001) A9(3.2,6.001) B1(-3.2,5.201) B2(-2.4,5.201) B3(-1.6,5.201) B7(1.6,5.201) B8(2.4,5.201) B9(3.2,5.201) C1(-3.2,4.401) C2(-2.4,4.401) C3(-1.6,4.401) C7(1.6,4.401) C8(2.4,4.401) C9(3.2,4.401) D1(-3.2,3.6) D2(-2.4,3.6) D3(-1.6,3.6) D7(1.6,3.6) D8(2.4,3.6) D9(3.2,3.6) E1(-3.2,2.8) E2(-2.4,2.8) E3(-1.6,2.8) E7(1.6,2.8) E8(2.4,2.8) E9(3.2,2.8) F1(-3.2,2) F2(-2.4,2) F3(-1.6,2) F7(1.6,2) F8(2.4,2) F9(3.2,2) G1(-3.2,1.2) G2(-2.4,1.2) G3(-1.6,1.2) G7(1.6,1.2) G8(2.4,1.2) G9(3.2,1.2) H1(-3.2,0.4) H2(-2.4,0.4) H3(-1.6,0.4) H7(1.6,0.4) H8(2.4,0.4) H9(3.2,0.4) J1(-3.2,-0.4) J2(-2.4,-0.4) J3(-1.6,-0.4) J7(1.6,-0.4) J8(2.4,-0.4) J9(3.2,-0.4) K1(-3.2,-1.2) K2(-2.4,-1.2) K3(-1.6,-1.2) K7(1.6,-1.2) K8(2.4,-1.2) K9(3.2,-1.2) L1(-3.2,-2) L2(-2.4,-2) L3(-1.6,-2) L7(1.6,-2) L8(2.4,-2) L9(3.2,-2) M1(-3.2,-2.8) M2(-2.4,-2.8) M3(-1.6,-2.8) M7(1.6,-2.8) M8(2.4,-2.8) M9(3.2,-2.8) N1(-3.2,-3.6) N2(-2.4,-3.6) N3(-1.6,-3.6) N7(1.6,-3.6) N8(2.4,-3.6) N9(3.2,-3.6) P1(-3.2,-4.401) P2(-2.4,-4.401) P3(-1.6,-4.401) P7(1.6,-4.401) P8(2.4,-4.401) P9(3.2,-4.401) R1(-3.2,-5.201) R2(-2.4,-5.201) R3(-1.6,-5.201) R7(1.6,-5.201) R8(2.4,-5.201) R9(3.2,-5.201) T1(-3.2,-6.001) T2(-2.4,-6.001) T3(-1.6,-6.001) T7(1.6,-6.001) T8(2.4,-6.001) T9(3.2,-6.001)
BGA153_P14_P5_11P5X13
  round 0.254 smd: A1(-3.25,3.25) A2(-2.75,3.25) A3(-2.25,3.25) A4(-1.75,3.25) A5(-1.25,3.25) A6(-0.75,3.25) A7(-0.25,3.25) A8(0.25,3.25) A9(0.75,3.25) A10(1.25,3.25) A11(1.75,3.25) A12(2.25,3.25) A13(2.75,3.25) A14(3.25,3.25) B1(-3.25,2.75) B2(-2.75,2.75) B3(-2.25,2.75) B4(-1.75,2.75) B5(-1.25,2.75) B6(-0.75,2.75) B7(-0.25,2.75) B8(0.25,2.75) B9(0.75,2.75) B10(1.25,2.75) B11(1.75,2.75) B12(2.25,2.75) B13(2.75,2.75) B14(3.25,2.75) C1(-3.25,2.25) C2(-2.75,2.25) C3(-2.25,2.25) C4(-1.75,2.25) C5(-1.25,2.25) C6(-0.75,2.25) C7(-0.25,2.25) C8(0.25,2.25) C9(0.75,2.25) C10(1.25,2.25) C11(1.75,2.25) C12(2.25,2.25) C13(2.75,2.25) C14(3.25,2.25) D1(-3.25,1.75) D2(-2.75,1.75) D3(-2.25,1.75) D4(-1.75,1.75) D12(2.25,1.75) D13(2.75,1.75) D14(3.25,1.75) E1(-3.25,1.25) E2(-2.75,1.25) E3(-2.25,1.25) E5(-1.25,1.25) E6(-0.75,1.25) E7(-0.25,1.25) E8(0.25,1.25) E9(0.75,1.25) E10(1.25,1.25) E12(2.25,1.25) E13(2.75,1.25) E14(3.25,1.25) F1(-3.25,0.75) F2(-2.75,0.75) F3(-2.25,0.75) F5(-1.25,0.75) F10(1.25,0.75) F12(2.25,0.75) F13(2.75,0.75) F14(3.25,0.75) G1(-3.25,0.25) G2(-2.75,0.25) G3(-2.25,0.25) G5(-1.25,0.25) G10(1.25,0.25) G12(2.25,0.25) G13(2.75,0.25) G14(3.25,0.25) H1(-3.25,-0.25) H2(-2.75,-0.25) H3(-2.25,-0.25) H5(-1.25,-0.25) H10(1.25,-0.25) H12(2.25,-0.25) H13(2.75,-0.25) H14(3.25,-0.25) J1(-3.25,-0.75) J2(-2.75,-0.75) J3(-2.25,-0.75) J5(-1.25,-0.75) J10(1.25,-0.75) J12(2.25,-0.75) J13(2.75,-0.75) J14(3.25,-0.75) K1(-3.25,-1.25) K2(-2.75,-1.25) K3(-2.25,-1.25) K5(-1.25,-1.25) K6(-0.75,-1.25) K7(-0.25,-1.25) K8(0.25,-1.25) K9(0.75,-1.25) K10(1.25,-1.25) K12(2.25,-1.25) K13(2.75,-1.25) K14(3.25,-1.25) L1(-3.25,-1.75) L2(-2.75,-1.75) L3(-2.25,-1.75) L12(2.25,-1.75) L13(2.75,-1.75) L14(3.25,-1.75) M1(-3.25,-2.25) M2(-2.75,-2.25) M3(-2.25,-2.25) M4(-1.75,-2.25) M5(-1.25,-2.25) M6(-0.75,-2.25) M7(-0.25,-2.25) M8(0.25,-2.25) M9(0.75,-2.25) M10(1.25,-2.25) M11(1.75,-2.25) M12(2.25,-2.25) M13(2.75,-2.25) M14(3.25,-2.25) N1(-3.25,-2.75) N2(-2.75,-2.75) N3(-2.25,-2.75) N4(-1.75,-2.75) N5(-1.25,-2.75) N6(-0.75,-2.75) N7(-0.25,-2.75) N8(0.25,-2.75) N9(0.75,-2.75) N10(1.25,-2.75) N11(1.75,-2.75) N12(2.25,-2.75) N13(2.75,-2.75) N14(3.25,-2.75) P1(-3.25,-3.25) P2(-2.75,-3.25) P3(-2.25,-3.25) P4(-1.75,-3.25) P5(-1.25,-3.25) P6(-0.75,-3.25) P7(-0.25,-3.25) P8(0.25,-3.25) P9(0.75,-3.25) P10(1.25,-3.25) P11(1.75,-3.25) P12(2.25,-3.25) P13(2.75,-3.25) P14(3.25,-3.25)
CONN3-PWR-PJ102A
  oval 1.778x4.572 hole 1.016x3.556: 1(0,0)
  oval 1.778x3.81 hole 1.016x3.048: 2(5.994,0)
  oval 3.81x1.778 hole 3.048x1.016: 3(2.997,4.699)
CONN19_HDMI
  rect 0.23x0.951 smd: 1(1.8,4.841) 3(1.4,4.841) 5(1,4.841) 7(0.6,4.841) 9(0.2,4.841) 11(-0.2,4.841) 13(-0.6,4.841) 15(-1,4.841) 17(-1.4,4.841) 19(-1.8,4.841)
  rect 0.23x1 smd: 2(1.6,3.54) 4(1.2,3.54) 6(0.8,3.54) 8(0.4,3.54) 10(0,3.54) 12(-0.4,3.54) 14(-0.8,3.54) 16(-1.2,3.54) 18(-1.6,3.54)
  oval 1.651x2.54 hole 0.381x1.27: 20(3.1,0) 21(-3.1,0)
  rect 2.413x1.524 smd: 22(3.45,3.36) 23(-3.45,3.36)
DCK5_2P15X1P4
  rect 0.4x0.9 smd: 1(-0.65,-1.1) 2(0,-1.1) 3(0.65,-1.1) 4(0.65,1.1) 5(-0.65,1.1)
DGN-16X60
  oval 0.406x1.524 smd: 1(-0.975,-2.311) 2(-0.325,-2.311) 3(0.325,-2.311) 4(0.975,-2.311) 5(0.975,2.311) 6(0.325,2.311) 7(-0.325,2.311) 8(-0.975,2.311)
  rect 2.032x2.032 smd: 9(0,0)
HEADER10X2_SMD
  rect 0.711x2.794 smd: 1(-5.715,-2.705) 2(-5.715,2.705) 3(-4.445,-2.705) 4(-4.445,2.705) 5(-3.175,-2.705) 6(-3.175,2.705) 7(-1.905,-2.705) 8(-1.905,2.705) 9(-0.635,-2.705) 10(-0.635,2.705) 11(0.635,-2.705) 12(0.635,2.705) 13(1.905,-2.705) 14(1.905,2.705) 15(3.175,-2.705) 16(3.175,2.705) 17(4.445,-2.705) 18(4.445,2.705) 19(5.715,-2.705) 20(5.715,2.705)
HEADER23X2
  rect 1.524x1.524 hole 0.889: 1(0,0)
  round 1.524 hole 0.889: 2(0,2.54) 3(2.54,0) 4(2.54,2.54) 5(5.08,0) 6(5.08,2.54) 7(7.62,0) 8(7.62,2.54) 9(10.16,0) 10(10.16,2.54) 11(12.7,0) 12(12.7,2.54) 13(15.24,0) 14(15.24,2.54) 15(17.78,0) 16(17.78,2.54) 17(20.32,0) 18(20.32,2.54) 19(22.86,0) 20(22.86,2.54) 21(25.4,0) 22(25.4,2.54) 23(27.94,0) 24(27.94,2.54) 25(30.48,0) 26(30.48,2.54) 27(33.02,0) 28(33.02,2.54) 29(35.56,0) 30(35.56,2.54) 31(38.1,0) 32(38.1,2.54) 33(40.64,0) 34(40.64,2.54) 35(43.18,0) 36(43.18,2.54) 37(45.72,0) 38(45.72,2.54) 39(48.26,0) 40(48.26,2.54) 41(50.8,0) 42(50.8,2.54) 43(53.34,0) 44(53.34,2.54) 45(55.88,0) 46(55.88,2.54)
LED_0603
  rect 0.762x1.016 smd: 1(-0.826,0) 2(0.826,0)
MICRO_SD_15X14_3X1_8MM
  rrect 0.6x1.88 smd: 1(8.8,-0.01) 2(7.7,-0.01) 3(6.6,-0.01) 4(5.5,-0.01) 5(4.4,-0.01) 6(3.3,-0.01) 7(2.2,-0.01) 8(1.1,-0.01)
  rrect 1.3x1.3 smd: 9(-0.85,1.58)
  rrect 1.3x1.4 smd: 10(-0.85,8.98)
  rrect 1.7x1.5 smd: S1(12.45,0)
  rrect 1.6x1.5 smd: S2(-0.325,0)
  rrect 1.5x1.7 smd: S3(-0.75,14.78) S4(12.75,14.78)
MTGH200C125D_PL
  round 4.445 hole 3.175: 1(0,0)
OSC4_61X65LS_79X98SMD
  rect 0.711x0.889 smd: 1(-0.826,-0.775) 2(0.826,-0.775) 3(0.826,0.775) 4(-0.826,0.775)
POLYSW200-5638-310
  round 1.651 hole 1.016: 1(-5.08,2.54) 2(0,0)
QFN32_5X5MM_EP3P3MM
  oval 0.254x0.838 smd: 1(-1.751,-2.515) 8(1.751,-2.515) 17(1.751,2.515) 24(-1.751,2.515)
  rect 0.254x0.838 smd: 2(-1.251,-2.515) 3(-0.751,-2.515) 4(-0.25,-2.515) 5(0.25,-2.515) 6(0.751,-2.515) 7(1.251,-2.515) 18(1.251,2.515) 19(0.751,2.515) 20(0.25,2.515) 21(-0.25,2.515) 22(-0.751,2.515) 23(-1.251,2.515)
  oval 0.838x0.254 smd: 9(2.515,-1.751) 16(2.515,1.751) 25(-2.515,1.751) 32(-2.515,-1.751)
  rect 0.838x0.254 smd: 10(2.515,-1.251) 11(2.515,-0.751) 12(2.515,-0.25) 13(2.515,0.25) 14(2.515,0.751) 15(2.515,1.251) 26(-2.515,1.251) 27(-2.515,0.751) 28(-2.515,0.25) 29(-2.515,-0.25) 30(-2.515,-0.751) 31(-2.515,-1.251)
  rect 3.404x3.404 smd: 33(0,0)
QFN64S9X9P5
  rect 0.6x0.25 smd: 1(-4.35,3.75) 2(-4.35,3.25) 3(-4.35,2.75) 4(-4.35,2.25) 5(-4.35,1.75) 6(-4.35,1.25) 7(-4.35,0.75) 8(-4.35,0.25) 9(-4.35,-0.25) 10(-4.35,-0.75) 11(-4.35,-1.25) 12(-4.35,-1.75) 13(-4.35,-2.25) 14(-4.35,-2.75) 15(-4.35,-3.25) 16(-4.35,-3.75) 33(4.35,-3.75) 34(4.35,-3.25) 35(4.35,-2.75) 36(4.35,-2.25) 37(4.35,-1.75) 38(4.35,-1.25) 39(4.35,-0.75) 40(4.35,-0.25) 41(4.35,0.25) 42(4.35,0.75) 43(4.35,1.25) 44(4.35,1.75) 45(4.35,2.25) 46(4.35,2.75) 47(4.35,3.25) 48(4.35,3.75)
  rect 0.25x0.6 smd: 17(-3.75,-4.35) 18(-3.25,-4.35) 19(-2.75,-4.35) 20(-2.25,-4.35) 21(-1.75,-4.35) 22(-1.25,-4.35) 23(-0.75,-4.35) 24(-0.25,-4.35) 25(0.25,-4.35) 26(0.75,-4.35) 27(1.25,-4.35) 28(1.75,-4.35) 29(2.25,-4.35) 30(2.75,-4.35) 31(3.25,-4.35) 32(3.75,-4.35) 49(3.75,4.35) 50(3.25,4.35) 51(2.75,4.35) 52(2.25,4.35) 53(1.75,4.35) 54(1.25,4.35) 55(0.75,4.35) 56(0.25,4.35) 57(-0.25,4.35) 58(-0.75,4.35) 59(-1.25,4.35) 60(-1.75,4.35) 61(-2.25,4.35) 62(-2.75,4.35) 63(-3.25,4.35) 64(-3.75,4.35)
  rect 5.08x5.08 smd: 65(0,0)
RD205SMD_250D
  rect 3.048x1.651 smd: 1(-2.603,0) 2(2.603,0)
RJ45-7499010211A
  round 1.016 hole 3.251 unplated: (-1.27,-6.35) (10.16,-6.35)
  rect 1.524x1.524 hole 1.016: 1(0,0)
  round 1.524 hole 1.016: 2(1.27,2.54) 3(2.54,0) 4(3.81,2.54) 5(5.08,0) 6(6.35,2.54) 7(7.62,0) 8(8.89,2.54) 9(-1.88,-11.252) 10(0.66,-9.728) 11(8.23,-11.252) 12(10.77,-9.728)
  round 2.286 hole 1.6: 13(-3.429,-3.302) 14(12.319,-3.302)
SIP6
  rect 1.524x1.524 hole 1.016: 1(0,0)
  round 1.524 hole 1.016: 2(0,-2.54) 3(0,-5.08) 4(0,-7.62) 5(0,-10.16) 6(0,-12.7)
SM-7351-IND-0805
  rect 1.397x1.549 smd: 1(-0.95,0) 2(0.95,0)
SMINI6-F3-B
  rect 0.305x0.95 smd: 1(0.65,0.75) 2(0,0.75) 3(-0.65,0.75) 4(-0.65,-0.75) 5(0,-0.75) 6(0.65,-0.75)
SO8-25X75
  oval 0.635x1.905 smd: 1(-1.905,-2.794) 2(-0.635,-2.794) 3(0.635,-2.794) 4(1.905,-2.794) 5(1.905,2.794) 6(0.635,2.794) 7(-0.635,2.794) 8(-1.905,2.794)
SOD323
  rect 0.8x0.8 smd: 1(1.125,0) 2(-1.125,0)
SOP8_DCT
  rect 0.305x1.6 smd: 1(-0.975,-1.702) 2(-0.325,-1.702) 3(0.325,-1.702) 4(0.975,-1.702) 5(0.975,1.702) 6(0.325,1.702) 7(-0.325,1.702) 8(-0.975,1.702)
SOT23-5
  rect 0.635x1.016 smd: 1(-0.953,-1.295) 2(0,-1.295) 3(0.953,-1.295) 4(0.953,1.295) 5(-0.953,1.295)
SW4SMD_63X161LS
  rect 0.889x1.016 smd: 1(-2.05,-0.8) 2(-2.05,0.8) 3(2.05,-0.8) 4(2.05,0.8)
TP1-8040
  round 1.524 hole 1.016: 1(0,0)
TP60C33D
  round 1.524 hole 0.889: 1(0,0)
TP60C_SMD
  round 1.27 smd: 1(0,0)
TSSOP10
  rect 0.305x1.905 smd: 1(-1,-1.981)
  rect 0.305x1.651 smd: 2(-0.5,-2.108) 3(0,-2.108) 4(0.5,-2.108) 5(1,-2.108) 6(1,2.108) 7(0.5,2.108) 8(0,2.108) 9(-0.5,2.108) 10(-1,2.108)
U_6_DRY
  rect 0.305x0.508 smd: 1(-0.5,-0.439) 2(0,-0.439) 3(0.5,-0.439) 4(0.5,0.439) 5(0,0.439) 6(-0.5,0.439)
U_8_DCU
  rect 0.254x1.27 smd: 1(-0.749,-1.473) 2(-0.249,-1.473) 3(0.249,-1.473) 4(0.749,-1.473) 5(0.749,1.473) 6(0.249,1.473) 7(-0.249,1.473) 8(-0.749,1.473)
U_48_RSL
  rect 0.8x0.2 smd: 1(-3.075,2.2) 2(-3.075,1.8) 3(-3.075,1.4) 4(-3.075,1) 5(-3.075,0.6) 6(-3.075,0.2) 7(-3.075,-0.2) 8(-3.075,-0.6) 9(-3.075,-1) 10(-3.075,-1.4) 11(-3.075,-1.8) 12(-3.075,-2.2) 25(3.075,-2.2) 26(3.075,-1.8) 27(3.075,-1.4) 28(3.075,-1) 29(3.075,-0.6) 30(3.075,-0.2) 31(3.075,0.2) 32(3.075,0.6) 33(3.075,1) 34(3.075,1.4) 35(3.075,1.8) 36(3.075,2.2)
  rect 0.2x0.8 smd: 13(-2.2,-3.075) 14(-1.8,-3.075) 15(-1.4,-3.075) 16(-1,-3.075) 17(-0.6,-3.075) 18(-0.2,-3.075) 19(0.2,-3.075) 20(0.6,-3.075) 21(1,-3.075) 22(1.4,-3.075) 23(1.8,-3.075) 24(2.2,-3.075) 37(2.2,3.075) 38(1.8,3.075) 39(1.4,3.075) 40(1,3.075) 41(0.6,3.075) 42(0.2,3.075) 43(-0.2,3.075) 44(-0.6,3.075) 45(-1,3.075) 46(-1.4,3.075) 47(-1.8,3.075) 48(-2.2,3.075)
  rect 4.05x4.05 smd: 49(-0.225,0.225)
unnamed
  round 1.016 smd: 1(0,0)
USB5MINI_4SHIELDED_SMD-5
  rect 1.4x0.5 smd: 1(0,1.6) 2(0,0.8) 3(0,0) 4(0,-0.8) 5(0,-1.6)
  rect 3.81x2.54 smd: 6(-2.4,4.2) 7(-2.4,-4.2)
  rect 0.8x2.35 smd: 8(-5.2,2.675) 9(-5.2,-2.675)
USB_A_SH
  round 1.651 hole 1.016: 1(0,0) 2(2.499,0) 3(4.501,0) 4(7,0)
  oval 2.032x3.429 hole 1.016x2.413: 5(-3.071,-2.71) 6(10.071,-2.71)
XTAL4_126-216SMD
  rect 1.27x1.905 smd: 1(-2.748,-1.6) 2(2.751,-1.6) 3(2.751,1.6) 4(-2.748,1.6)
XTAL150SMD_125X196
  rect 1.778x2.159 smd: 1(-1.9,0) 2(1.9,0)

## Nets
DGND: C1.1 C2.1 C3.1 C4.1 C5.2 C7.1 C8.1 C9.1 C10.1 C11.1 C12.1 C13.1 C14.1 C15.1 C16.2 C17.2 C18.2 C19.2 C20.2 C23.2 C24.2 C27.2 C28.2 C29.2 C30.2 C34.2 C35.2 C36.2 C37.2 C38.2 C39.1 C40.1 C41.2 C42.2 C43.2 C44.2 C45.2 C46.2 C47.2 C48.2 C49.2 C50.2 C51.2 C52.2 C53.2 C54.2 C55.1 C56.1 C57.1 C58.2 C59.2 C60.1 C61.1 C62.1 C63.2 C64.2 C65.2 C66.2 C67.2 C68.1 C69.1 C70.1 C71.1 C72.1 C73.1 C74.1 C75.1 C76.1 C77.2 C78.2 C79.2 C80.2 C81.2 C82.2 C83.2 C84.2 C85.2 C86.2 C87.2 C88.2 C89.2 C90.2 C91.2 C92.2 C94.2 C95.1 C96.1 C97.2 C98.2 C99.2 C100.2 C101.2 C102.2 C103.2 C104.2 C105.2 C106.2 C107.2 C108.2 C109.2 C110.2 C111.2 C112.2 C113.2 C114.2 C115.2 C116.2 C117.2 C118.1 C119.2 C120.2 C121.2 C122.1 C123.2 C124.2 C125.2 C126.1 C127.2 C128.2 C129.2 C130.2 C131.2 C132.2 C133.1 C134.2 C135.2 C136.2 C137.2 C138.2 C139.2 C140.2 C141.2 C142.2 C143.2 C144.2 C145.2 C146.2 C147.2 C148.2 C149.2 C150.2 C151.2 C152.2 C153.2 C154.2 C155.1 C156.2 C157.2 C158.2 C159.2 C160.2 C161.2 C162.2 C163.2 C164.2 C165.2 C166.2 C167.2 C168.2 C169.2 C170.2 C171.2 C172.2 C173.2 C174.2 C175.2 D6.3 D6.8 D7.3 D7.8 FB3.2 J1.1 P1.2 P2.4 P2.8 P2.10 P2.12 P2.16 P2.20 P3.4 P4.5 P5.8 P6.4 P6.7 P6.10 P6.13 P6.16 P8.1 P8.2 P9.1 P9.2 P9.43 P9.44 P9.45 P9.46 P10.6(VSS) P10.9 Q1.1 Q1.4 Q2.1 Q2.4 R10.2 R12.1 R22.1 R25.2 R29.2 R49.1 R53.2 R54.1 R76.2 R77.2 R78.2 R79.2 R80.2 R81.2 R82.2 R83.2 R84.2 R85.2 R86.2 R87.2 R88.2 R89.2 R90.2 R91.2 R92.2 R93.2 R94.2 R95.2 R96.1 R99.1 R100.2 R115.2 R116.2 R117.2 R118.2 R130.1 R132.1 R135.2 R136.1 R144.2 R145.2 R148.2 R149.2 R164.2 R165.2 S1.1 S1.3 S2.2 S2.4(B2) S3.1 S3.3 TP1.1(TP) TP8.1(TP) U1.3 U2.30 U2.41 U2.49 U3.3 U4.5 U4.6 U4.7 U4.8 U5.A1 U5.A18 U5.F8 U5.G8 U5.G9 U5.G11 U5.G12 U5.H6 U5.H7 U5.H8 U5.H9 U5.H10 U5.H12 U5.J6 U5.J7 U5.J8 U5.J9 U5.J10 U5.J11 U5.K7 U5.K9 U5.K10 U5.K11 U5.L10 U5.L11 U5.L12 U5.L13 U5.M6 U5.M7 U5.M8 U5.M9 U5.M10 U5.M12 U5.M14(VSSA_USB2) U5.N7 U5.N10 U5.N11 U5.N14 U5.V1 U5.V18 U6.4 U7.2 U8.1 U8.9(PAD) U9.4 U10.4 U11.8 U11.9 U11.16 U11.17 U11.18 U11.19 U11.53 U11.54 U11.61 U11.62 U11.63 U11.65 U12.A9 U12.B1 U12.B3 U12.B9 U12.D1 U12.D8 U12.E1 U12.E2 U12.E8 U12.F9 U12.G1 U12.G8 U12.G9 U12.J2 U12.J8 U12.M1 U12.M9 U12.P1 U12.P9 U12.T1 U12.T9 U13.A6 U13.C4(VSSQ4) U13.E7 U13.G5 U13.H10 U13.J5 U13.K8 U13.N2 U13.N5 U13.P4 U13.P6 U14.33 U15.1 U15.4 U16.3 Y4.2
GND_EARTH: MTG1.1(TP) MTG2.1(TP) MTG3.1(TP) MTG4.1(TP) P3.5(SHELD1) P3.6 P4.6 P4.7 P4.8 P4.9 P5.13 P5.14 P6.20 P6.21 P6.22 P6.23 P10.S1 P10.S3 P10.S4 R136.2
GND_OSC0: C25.2 C26.2 R29.1 R30.1 U5.V11
GND_OSC1: C21.1 C22.1 R30.2 U5.A5
GNDA_ADC: C31.2 C32.2 C33.2 C93.2 FB3.1 P9.34 U5.A9 U5.E8
VBUS: FB7.2 P3.1
VDD_1V8: C14.2 C78.1 C86.1 C88.1 FB1.1 FB2.2 FB5.2 R9.2 U2.40 U5.D10 U5.E9 U5.N16 U5.R16
VDD_3V3A: C15.2 C27.1 C37.1 C38.1 C56.2 C57.2 C58.1 C59.1 C60.2 C61.2 C66.1 C67.1 C68.2 C69.2 C70.2 C71.2 C72.2 C73.2 C74.2 C75.2 C76.2 C77.1 C87.1 C152.1 C158.1 C159.1 R1.1 R3.1 R4.1 R14.1 R52.1 R55.1 R56.1 R57.1 R58.1 R59.1 R60.1 R61.1 R62.1 R63.1 R64.1 R65.1 R66.1 R67.1 R68.1 R69.1 R70.1 R156.1 U2.43 U3.5 U4.1 U5.E10 U5.E11 U5.E12 U5.E13 U5.F14 U5.G14 U5.H14 U5.J14 U5.K14 U5.L14 U5.N5 U5.N15 U5.P5 U5.P6 U5.P7 U5.P8 U5.P10 U5.P11 U5.P12 U5.P13 U5.R15 U6.6 U6.7 U6.8(VCC) U7.4 Y4.4(VCC)
VDD_3V3AUX: C18.1 D1.2 U2.1
VDD_3V3B: C20.1 C23.1 C29.1 C126.2 C127.1 C128.1 C129.1 C130.1 C135.1 C153.1 C154.1 C155.2 FB4.1 P2.5(TVDD) P9.3 P9.4 P10.4 R11.1 R23.1 R24.1 R33.1 R34.1 R101.1 R102.1 R103.1 R104.1 R105.1 R106.1 R107.1 R108.1 R109.1 R110.1 R111.1 R112.2 R113.2 R114.2 R119.1 R150.1 R151.1 R152.1 R153.1 R154.1 R155.1 R157.2 R158.1 R163.1 R166.2 U1.5 U4.3(OUT) U13.C6 U13.E6 U13.F5 U13.J10 U13.K9 U13.M4 U13.N4 U13.P3 U13.P5 U14.12 U15.7 U15.8(VCC)
VDD_5V: C2.2 P1.1 P9.5 P9.6 U2.10
VDD_ADC: C93.1 FB2.1 P9.32 R27.1 U5.D8
VDD_CORE: C11.2 C39.2 C40.2 C41.1 C42.1 C43.1 C44.1 C45.1 C46.1 C47.1 C48.1 C49.1 C50.1 C51.1 C52.1 C53.1 C54.1 C55.2 L3.2 U2.29 U5.F6 U5.F7 U5.G6 U5.G7 U5.G10 U5.H11 U5.J12 U5.K6 U5.K8 U5.K12 U5.L6 U5.L7 U5.L8 U5.L9 U5.M11 U5.M13 U5.N8 U5.N9 U5.N12 U5.N13
VDD_MPU: C12.2 C62.2 C63.1 C64.1 C65.1 L2.2 U2.24 U5.F10 U5.F11 U5.F12 U5.F13 U5.G13 U5.H13 U5.J13
VDD_MPUON: TP2.1(TP) U5.A2
VDD_PHYA: C131.1 C132.1 C133.2 FB4.2 R120.2 R121.2 R122.2 R123.2 R137.2 U14.1 U14.27
VDD_PLL: C79.1 C92.1 C94.1 C106.1 FB1.2 U5.E7 U5.H15 U5.R10 U5.R11
VDD_RTC: C104.1 U5.D6
VDDS: C80.1 C81.1 C82.1 C83.1 C84.1 C85.1 R8.2 R9.1 U5.E6 U5.E14 U5.F9 U5.K13 U5.N6 U5.P9 U5.P14
VDDS_DDR: C9.2 C95.2 C96.2 C97.1 C98.1 C99.1 C100.1 C101.1 C102.1 C103.1 C107.1 C108.1 C109.1 C110.1 C111.1 C112.1 C113.1 C114.1 C115.1 C116.1 C117.1 C118.2 C119.1 C120.1 C121.1 C122.2 R6.2 R97.1 R98.1 U5.E5 U5.F5 U5.G5 U5.H5 U5.J5 U5.K5 U5.L5 U12.A1 U12.A8 U12.B2 U12.C1 U12.C9 U12.D2 U12.D9 U12.E9 U12.F1 U12.G7 U12.H2 U12.H9 U12.K2 U12.K8 U12.N1 U12.N9 U12.R1 U12.R9
12M_LOOP: U6.2 U6.3
12MHZ: R21.2 U11.27
AIN0: P9.39 U5.B6
AIN1: P9.40 U5.C7
AIN2: P9.37 U5.B7
AIN3: P9.38 U5.A7
AIN4: P9.33 U5.C8
AIN5: P9.36 U5.B8
AIN6: P9.35 U5.A8
AIN7: R163.2 R164.1 U5.C9
AM3_MMC1_CLK: R35.1 U5.U9
AM3_MMC1_CMD: R36.1 U5.V9
AM3_MMC1_DAT0: R43.1 U5.U7
AM3_MMC1_DAT1: R44.1 U5.V7
AM3_MMC1_DAT2: R168.1 U5.R8
AM3_MMC1_DAT3: R169.1 U5.T8
AM3_MMC1_DAT4: R170.1 U5.U8
AM3_MMC1_DAT5: R171.1 U5.V8
AM3_MMC1_DAT6: R172.1 U5.R9
AM3_MMC1_DAT7: R173.1 U5.T9
B_UART0_RX: J1.4 R165.1 U15.2
B_UART0_TX: J1.5 U15.3
CAP_VBB_MPU: C91.1 U5.C10
CAP_VDD_SRAM_CORE: C89.1 U5.D9
CAP_VDD_SRAM_MPU: C90.1 U5.D11
CLKOUT2: P2.18 P9.41 R19.2 R20.1
CLKOUT_SRC: R19.1 U5.D14
CRS: R139.2 U14.14
DDR_A0: U5.F3 U12.N3
DDR_A1: U5.H1 U12.P7
DDR_A2: U5.E4 U12.P3
DDR_A3: U5.C3 U12.N2
DDR_A4: U5.C2 U12.P8
DDR_A5: U5.B1 U12.P2
DDR_A6: U5.D5 U12.R8
DDR_A7: U5.E2 U12.R2
DDR_A8: U5.D4 U12.T8
DDR_A9: U5.C1 U12.R3
DDR_A10: U5.F4 U12.L7
DDR_A11: U5.F2 U12.R7
DDR_A12: U5.E3 U12.N7
DDR_A13: U5.H3 U12.T3
DDR_A14: U5.H4 U12.T7
DDR_A15: U5.D3 U12.M7
DDR_BA0: U5.C4 U12.M2
DDR_BA1: U5.E1 U12.N8
DDR_BA2: U5.B3 U12.M3
DDR_CASN: U5.F1 U12.K3
DDR_CKE: R96.2 U5.G3 U12.K9
DDR_CLK: U5.D2 U12.J7
DDR_CLKN: U5.D1 U12.K7
DDR_CSN: U5.H2 U12.L2
DDR_D0: U5.M3 U12.E3
DDR_D1: U5.M4 U12.F7
DDR_D2: U5.N1 U12.F2
DDR_D3: U5.N2 U12.F8
DDR_D4: U5.N3 U12.H3
DDR_D5: U5.N4 U12.H8
DDR_D6: U5.P3 U12.G2
DDR_D7: U5.P4 U12.H7
DDR_D8: U5.J1 U12.D7
DDR_D9: U5.K1 U12.C3
DDR_D10: U5.K2 U12.C8
DDR_D11: U5.K3 U12.C2
DDR_D12: U5.K4 U12.A7
DDR_D13: U5.L3 U12.A2
DDR_D14: U5.L4 U12.B8
DDR_D15: U5.M1 U12.A3
DDR_DQM0: U5.M2 U12.E7
DDR_DQM1: U5.J2 U12.D3
DDR_DQS0: U5.P1 U12.F3
DDR_DQS1: U5.L1 U12.C7
DDR_DQSN0: U5.P2 U12.G3
DDR_DQSN1: U5.L2 U12.B7
DDR_ODT: U5.G1 U12.K1
DDR_RASN: U5.G4 U12.J3
DDR_RESETN: R97.2 U5.G2 U12.T2
DDR_VREF: C28.1 C123.1 C124.1 R98.2 R100.1 U5.J4 U12.H1 U12.M8
DDR_VTP: R22.2 U5.J3
DDR_WEN: U5.B2 U12.L3
DVI_+5V: P6.19 R146.1 R147.1 RT1.2
EHRPWM1A: P9.14 U5.U14
EHRPWM1B: P9.16 U5.T14
EHRPWM2A: P8.19 U5.U10
EHRPWM2B: P8.13 U5.T10
EMMC_RSTN: R111.2 R162.2 U13.K5
EMMC_VCCI: C125.1 U13.C2
ENZ_KALDO_1P8V: R54.2 U5.B4
ETH_RESETN: C174.1 R33.2 U1.4(Y) U14.19
ETH_RST_GPIO1_8: R34.2 U1.1 U5.E18
ETH_TXD4: R145.1 U14.18
GPIO0_7: P9.42 R50.1 R51.1
GPIO0_7SRC: R50.2 U5.C18
GPIO0_26: P8.14 U5.T11
GPIO0_27: P8.17(9) U5.U12
GPIO1_12: P8.12 U5.T12
GPIO1_13: P8.11 U5.R12
GPIO1_14: P8.16 U5.V13
GPIO1_15: P8.15 U5.U13
GPIO1_16: P9.15 R160.2 R161.2
GPIO1_17: P9.23 U5.V14
GPIO1_28: P9.12 U5.U18
GPIO1_29: P8.26 U5.V6
GPIO2_1: P8.18 U5.V12
GPIO3_18: R51.2 U5.B12
GPIO3_19: P9.27 U5.C13
GPIO3_20: R20.2 U5.D13
GPIO3_21: P9.25 R167.2 U5.A14
GRN_C: P5.10 R132.2
GRNA: P5.9 U14.3
HDMI_1V8: C144.1 C145.1 C146.1 C147.1 C148.1 C149.1 C150.1 C151.1 FB5.1 U11.5 U11.14 U11.29 U11.35 U11.36 U11.41 U11.46 U11.47 U11.48 U11.55
HDMI_CEC: D8.1(CATHODE) P6.15 U11.30
HDMI_CEC_D: D8.2 R166.1
HDMI_DSCL: P6.17 R146.2 U11.33
HDMI_DSDA: P6.18(SDA) R147.2 U11.32
HDMI_HPD: P6.1 U11.31
HDMI_INT: R158.2 U5.U16 U11.50
HDMI_SWING: R148.1 U11.34
HDMI_TX0+: D6.2 P6.9 U11.40
HDMI_TX0-: D6.1 P6.11 U11.39
HDMI_TX1+: D7.5 P6.6 U11.43
HDMI_TX1-: D7.4 P6.8 U11.42
HDMI_TX2+: D7.2 P6.3 U11.45
HDMI_TX2-: D7.1 P6.5 U11.44
HDMI_TXC+: D6.4 P6.12 U11.38
HDMI_TXC-: D6.5 P6.14 U11.37
HDMICLK_DISN: U5.V17 Y4.1
I2C0_SCL: R3.2 U2.28 U5.C16 U7.1 U11.52
I2C0_SDA: R4.2 U2.27 U5.C17 U7.3 U11.51
I2C1_SCL: P9.17(9) U5.A16
I2C1_SDA: P9.18 U5.B16
I2C2_SCL: P9.19 U5.D17
I2C2_SDA: P9.20 U5.D18
JTAG_EMU0: P2.13 R23.2 U5.C14
JTAG_EMU1: P2.14 R24.2 U5.B14
JTAG_TCK: P2.9 P2.11 U5.A12
JTAG_TDI: P2.3 U5.B11
JTAG_TDO: P2.7 U5.A11
JTAG_TMS: P2.1 U5.C11
JTAG_TRSTN: P2.2 R25.1 U5.B10
LCD_DATA0: C173.1 P8.45 R70.2 R95.1 U5.R1 U11.15
LCD_DATA1: C171.1 P8.46 R69.2 R94.1 U5.R2 U11.13
LCD_DATA2: C172.1 P8.43 R68.2 R75.1 R93.1 U5.R3 U11.12
LCD_DATA3: C170.1 P8.44 R67.2 R92.1 U5.R4 U11.11
LCD_DATA4: C169.1 P8.41 R66.2 R91.1 U5.T1 U11.10
LCD_DATA5: C163.1 P8.42 R65.2 R90.1 U5.T2 U11.7
LCD_DATA6: C162.1 P8.39 R64.2 R89.1 U5.T3 U11.6
LCD_DATA7: C161.1 P8.40 R63.2 R88.1 U5.T4 U11.3
LCD_DATA8: C160.1 P8.37 R62.2 R87.1 U5.U1 U11.2
LCD_DATA9: C157.1 P8.38 R61.2 R86.1 U5.U2 U11.1
LCD_DATA10: C156.1 P8.36 R60.2 R85.1 U5.U3 U11.64
LCD_DATA11: C168.1 P8.34 R59.2 R84.1 U5.U4 U11.60
LCD_DATA12: C167.1 P8.35 R58.2 R83.1 U5.V2 U11.59
LCD_DATA13: C166.1 P8.33 R57.2 R82.1 U5.V3 U11.58
LCD_DATA14: C165.1 P8.31 R56.2 R81.1 U5.V4 U11.57
LCD_DATA15: C164.1 P8.32 R55.2 R80.1 U5.T5 U11.56
LCD_DE: P8.30 R48.2 U11.20
LCD_HSYNC: P8.29 R47.2 U11.22
LCD_PCLK: P8.28 R45.2 U11.4
LCD_VSYNC: P8.27 R46.2 U11.21(VSYNC/VREF)
LCDDE: R48.1 U5.R6
LCDPCLK: R45.1 U5.V5
LCDVHYNC: R47.1 U5.R5
LCDVSYNC: R46.1 U5.U5
LDO_PGOOD: U2.46 U5.B5
LEDAA: D2.2 R72.2
LEDAC: D2.1(C) Q1.6
LEDBA: D3.2 R73.2
LEDBC: D3.1(C) Q1.3
LEDCA: D4.2 R74.2
LEDCC: D4.1(C) Q2.6
LEDDA: D5.2 R71.2
LEDDC: D5.1(C) Q2.3
MDIO_CLK: U5.M18 U14.17
MDIO_DATA: R119.2 U5.M17 U14.16
MII1_COL: R138.1 U5.H16
MII1_CRS_DV: R139.1 U5.H17
MII1_REFCLK: R28.2 R124.1 R140.1
MII1_RXCLK: R131.1 U5.L18
